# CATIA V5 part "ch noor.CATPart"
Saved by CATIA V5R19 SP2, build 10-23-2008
Part number: ch noor
Bounding box of the stored display mesh (mm): x 1500.359 to 1817.764, y -612.612 to 612.612, z 346.531 to 516.162
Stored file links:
  C:\BEHROOZ\catia learning\tarh haye mashin\hb\ch noor.CATPart
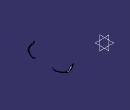
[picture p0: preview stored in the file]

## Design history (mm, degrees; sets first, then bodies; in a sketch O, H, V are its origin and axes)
Body1 (main body)
  Plane1: stored without definition
  DatumSurface1
  Plane2: stored without definition
  Sketch1 on Plane1, origin (1983, 0, 0), H (0, 1, 0), V (0, 0, 1)
    arc A1 centre (238.5413, 303.3655) radius 92.0127 from (249.9953, 394.6625) to (292.3812, 377.9819) cw
    arc A2 centre (368.3519, 471.1615) radius 120.2248 from (292.3812, 377.9819) to (302.9791, 370.2636) ccw
    arc A3 centre (528.6384, 453.5988) radius 72.5322 from (555.5979, 386.263) to (583.1819, 405.7874) ccw
    arc A4 centre (561.3367, 423.9448) radius 28.4061 from (583.1819, 405.7874) to (587.8719, 434.0831) ccw
    line L1 (587.8719, 434.0831) -> (572.2717, 462.2879)
    line L2 (571.7299, 482.1301) -> (588.1958, 516.1623)
    arc A5 centre (755.1509, 528.0737) radius 167.3794 from (588.1958, 516.1623) to (596.0761, 476.0056) ccw
    arc A6 centre (506.4887, 415.5977) radius 106.1308 from (601.3614, 463.168) to (612.6122, 416.8522) cw
    arc A7 centre (570.0311, 416.3488) radius 42.584 from (612.6122, 416.8522) to (581.1936, 375.2539) cw
    arc A8 centre (345.1579, 1330.4125) radius 983.8907 from (581.1936, 375.2539) to (349.5086, 346.5314) cw
    arc A9 centre (349.1879, 419.0478) radius 72.5171 from (349.5086, 346.5314) to (307.5344, 359.6869) cw
    arc A10 centre (495.3667, 627.3692) radius 327.0089 from (307.5344, 359.6869) to (281.8572, 379.683) cw
    arc A11 centre (239.0681, 330.0446) radius 65.5353 from (281.8572, 379.683) to (249.9953, 394.6625) ccw
    arc A12 centre (685.0375, 505.1243) radius 93.6057 from (596.0761, 476.0056) to (601.3614, 463.168) ccw
    arc A13 centre (426.9201, 700.8657) radius 339.9012 from (555.5979, 386.263) to (473.4383, 364.1628) cw
    arc A14 centre (372.1296, 1042.3373) radius 685.6998 from (473.4383, 364.1628) to (344.0017, 357.2147) cw
    arc A15 centre (347.349, 438.7451) radius 81.599 from (344.0017, 357.2147) to (302.9791, 370.2636) cw
    arc A16 centre (591.1542, 472.7319) radius 21.5784 from (572.2717, 462.2879) to (571.7299, 482.1301) cw
  Sketch2 on Plane2, origin (1983, 0, 0), H (0, 1, 0), V (0, 0, 1)
    arc A1 centre (-239.0678, 330.0441) radius 65.5358 from (-281.8572, 379.683) to (-249.9953, 394.6625) cw
    arc A2 centre (-495.4023, 627.4149) radius 327.0667 from (-281.8572, 379.683) to (-307.5344, 359.6869) cw
    arc A3 centre (-349.1882, 419.0488) radius 72.518 from (-307.5344, 359.6869) to (-349.5086, 346.5314) cw
    arc A4 centre (-345.1579, 1330.4128) radius 983.891 from (-349.5086, 346.5314) to (-581.1936, 375.2539) cw
    arc A5 centre (-570.0314, 416.3487) radius 42.5838 from (-581.1936, 375.2539) to (-612.6122, 416.8522) cw
    arc A6 centre (-506.4883, 415.5976) radius 106.1313 from (-612.6122, 416.8522) to (-601.3614, 463.168) cw
    arc A7 centre (-685.0715, 505.1383) radius 93.6424 from (-596.0761, 476.0056) to (-601.3614, 463.168) cw
    arc A8 centre (-755.1509, 528.0737) radius 167.3795 from (-588.1958, 516.1623) to (-596.0761, 476.0056) cw
    line L1 (-588.1958, 516.1623) -> (-571.7299, 482.1301)
    arc A9 centre (-591.1541, 472.7319) radius 21.5784 from (-571.7299, 482.1301) to (-572.2717, 462.2879) cw
    line L2 (-572.2717, 462.2879) -> (-587.8719, 434.0831)
    arc A10 centre (-561.3367, 423.9448) radius 28.406 from (-583.1819, 405.7874) to (-587.8719, 434.0831) cw
    arc A11 centre (-528.6382, 453.5991) radius 72.5325 from (-555.5979, 386.263) to (-583.1819, 405.7874) cw
    arc A12 centre (-426.9201, 700.8659) radius 339.9013 from (-473.4383, 364.1628) to (-555.5979, 386.263) cw
    arc A13 centre (-372.1296, 1042.3374) radius 685.6998 from (-344.0017, 357.2147) to (-473.4383, 364.1628) cw
    arc A14 centre (-347.3492, 438.7457) radius 81.5996 from (-302.9791, 370.2636) to (-344.0017, 357.2147) cw
    arc A15 centre (-368.367, 471.1822) radius 120.2503 from (-292.3812, 377.9819) to (-302.9791, 370.2636) cw
    arc A16 centre (-238.5411, 303.365) radius 92.0132 from (-292.3812, 377.9819) to (-249.9953, 394.6625) cw
  DatumSurface2
  Pad1: profile Sketch1, direction (1, 0, 0), up to face of DatumSurface2, offset 10
  DatumSurface3
  Pad2: profile Sketch2, direction (1, 0, 0), up to face of DatumSurface3, offset 10
  DatumSurface4
  Offset1: Offset DatumSurface4, Length 0
  DatumSurface5
  Offset2: Offset DatumSurface5, Length 0
  Translate1: ToTransfor Offset1, Direction (1, 0, 0), Length -8
  Translate2: Direction (1, 0, 0), Length -8, ToTransfor Offset2
  Split1: SplitPlane Translate1
  Split2: SplitPlane Translate2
